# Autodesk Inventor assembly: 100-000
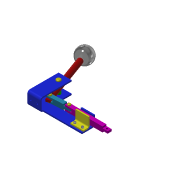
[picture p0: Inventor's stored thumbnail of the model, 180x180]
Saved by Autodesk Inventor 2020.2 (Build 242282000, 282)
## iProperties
Created: 2014-01
Part Number: 100-000
Document SubType Name: Assembly
Designer: F.Stasiak
Manager: www.cadconsulting.pl
Company: Fabian Stasiak CAD Consulting
Author: F.Stasiak
Subject: Zbiór ćwiczeń. Autodesk Inventor 2020. Kurs podstawowy
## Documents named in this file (11)
- C:\2020_Kurs_podstawowy\R6 Zespoły\Warsztat\Gotowe\100-000_Gotowy_W.iam
- C:\2020_Kurs_podstawowy\R6 Zespoły\Warsztat\Komponenty\100-002.ipt
- C:\2020_Kurs_podstawowy\R6 Zespoły\Warsztat\Komponenty\100-003.ipt
- C:\2020_Kurs_podstawowy\R6 Zespoły\Warsztat\Komponenty\100-004.ipt
- C:\2020_Kurs_podstawowy\R6 Zespoły\Warsztat\Komponenty\100-005.ipt
- C:\2020_Kurs_podstawowy\R6 Zespoły\Warsztat\Komponenty\100-006.ipt
- C:\2020_Kurs_podstawowy\R6 Zespoły\Warsztat\Komponenty\100-007.ipt
- C:\2020_Kurs_podstawowy\R6 Zespoły\Warsztat\Komponenty\100-008.ipt
- C:\2020_Kurs_podstawowy\R6 Zespoły\Warsztat\Komponenty\100-009.ipt
- C:\2020_Kurs_podstawowy\Zasoby\Content Center Files\pl-PL\ISO 4762(2)\ISO 4762 - M5 x 12ISO.ipt
- C:\2020_Kurs_podstawowy\R6 Zespoły\Warsztat\Komponenty\100-001G.ipt
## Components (13 placed, 10 different names)
1. 100-001G:1 — NAPĘD, Zestawiający:1, Zestawiający:2, Wstaw:1, Wstaw:3, Zestawiający:3, Zestawiający:4, Równoległy:1, Zestawiający:5
2. 100-002:1 — NAPĘD, Zestawiający:1, Zestawiający:2, Wstaw:2, Wstaw:4, Wstaw:6
3. 100-003:1 — Wstaw:1
4. 100-003:2 — Wstaw:2
5. 100-004:1 — Wstaw:3
6. 100-005:1 — Wstaw:4, Wstaw:5, Wstaw:7
7. 100-006:1 — Wstaw:5, Zestawiający:3, Wstaw:8
8. 100-007:1 — Zestawiający:4, Równoległy:1, Zestawiający:5
9. 100-008:1 — Wstaw:6
10. 100-009:1 — Wstaw:7
11. 100-009:2 — Wstaw:8
12. ISO 4762 M5 x 12:1
13. ISO 4762 M5 x 12:2
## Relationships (15: Insert 8, Mate 5, Angle 1, Flush 1)
- NAPĘD [Angle]: 100-001G:1 ↔ 100-002:1
- Zestawiający:1 [Mate]: 100-001G:1 ↔ 100-002:1
- Zestawiający:2 [Mate]: 100-001G:1 ↔ 100-002:1
- Wstaw:1 [Insert]: 100-001G:1 ↔ 100-003:1
- Wstaw:2 [Insert]: 100-002:1 ↔ 100-003:2
- Wstaw:3 [Insert]: 100-001G:1 ↔ 100-004:1
- Wstaw:4 [Insert]: 100-002:1 ↔ 100-005:1
- Wstaw:5 [Insert]: 100-005:1 ↔ 100-006:1
- Zestawiający:3 [Mate]: 100-001G:1 ↔ 100-006:1
- Zestawiający:4 [Mate]: 100-001G:1 ↔ 100-007:1
- Równoległy:1 [Flush]: 100-001G:1 ↔ 100-007:1
- Zestawiający:5 [Mate]: 100-001G:1 ↔ 100-007:1
- Wstaw:6 [Insert]: 100-002:1 ↔ 100-008:1
- Wstaw:7 [Insert]: 100-005:1 ↔ 100-009:1
- Wstaw:8 [Insert]: 100-006:1 ↔ 100-009:2
